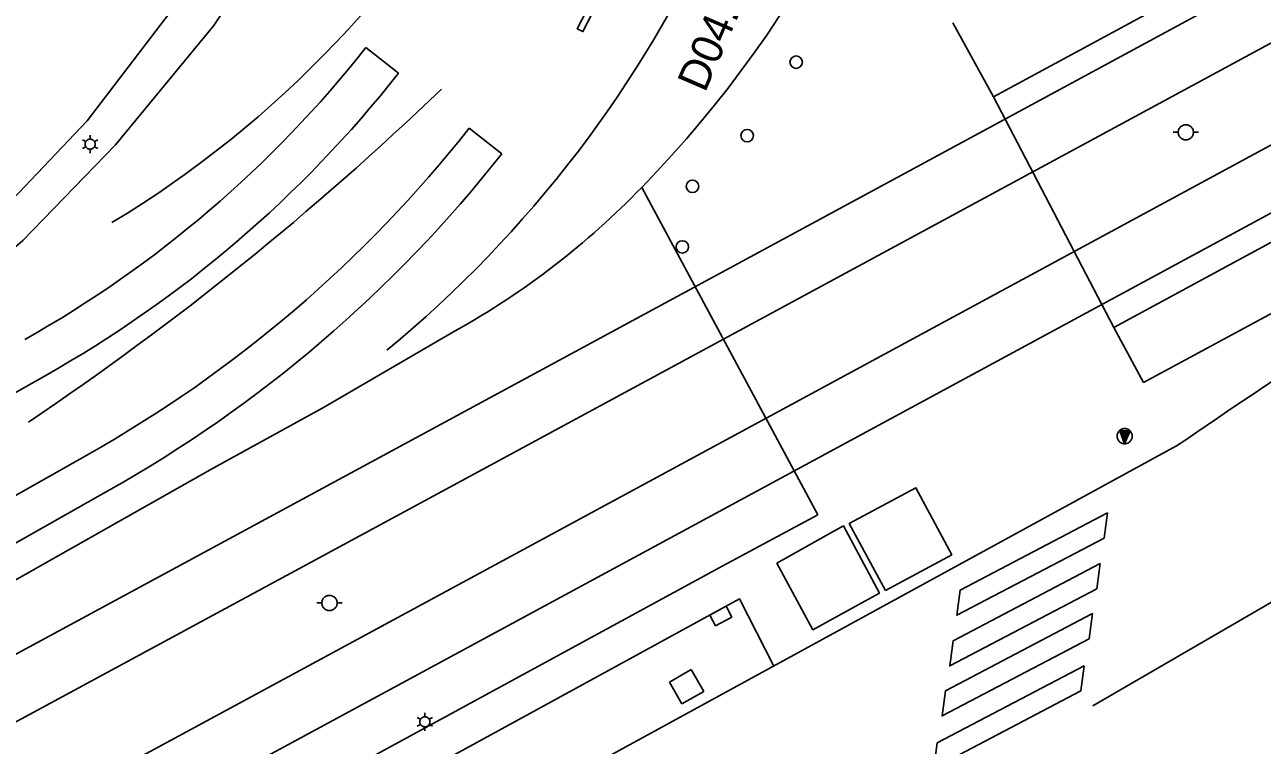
# Model space of a CAD drawing. Extents: x 81065 to 81486, y 452384 to 452681.
# Drawn here: x 81209.97 to 81239.76, y 452476.31 to 452493.67 of the extents above; entities that cross this region are included whole.
import ezdxf

# ---------------------------------------------------------------- set-up
doc = ezdxf.new("R2010")
doc.units = 0
for name, color, linetype in [('B-BH-IE-MEUBILAIR-WEGMEUBILAIR-VERKEERSBORD-S', 7, 'Continuous'), ('B-BH-IE-MEUBILAIR_WEGMEUBILAIR_LICHTMAST-S', 7, 'Continuous'), ('B-BH-IE-MEUBILAIR_WEGMEUBILAIR_PAAL-S', 7, 'Continuous'), ('B-BH-IE-MEUBILAIR_WEGMEUBILAIR_TRAMMAST-S', 7, 'Continuous'), ('B-BH-RI-GWA_RIOOLPUT-S', 7, 'Continuous'), ('B-BH-VH-KANTOPSLUITING-GV', 7, 'Continuous'), ('B-SB-OG-WEG_SPOOR_TRAM-G', 7, 'Continuous'), ('B-SRI-KOLK_COMBINATIE-S', 7, 'Continuous'), ('B-WE-VW-MARKERING_DWARS_OVERSTEEK_VOETGANGERS-G', 7, 'Continuous'), ('B-WE-VW-MARKERING_LANGS_STREEP_11_010-G', 7, 'Continuous'), ('B-WE-VW-MARKERING_LANGS_STREEP_13_010-G', 7, 'Continuous'), ('B-WE-VW-MARKERING_LANGS_STREEP_13_030-G', 7, 'Continuous'), ('B-WE-VW-MARKERING_PIJL-S', 7, 'Continuous'), ('N-OI-KL-VRI_LUS_DETECTIE-G', 7, 'Continuous'), ('N-OI-KL-VRI_LUS_DETECTIE-T18', 7, 'Continuous')]:
    doc.layers.add(name, color=color, linetype=linetype)

msp = doc.modelspace()

# ---------------------------------------------------------------- linework, layer by layer
at = {"layer": 'B-BH-IE-MEUBILAIR-WEGMEUBILAIR-VERKEERSBORD-S'}
for p, q in [((81236.318, 452483.879), (81236.583, 452483.879)), ((81236.45, 452483.57), (81236.34, 452483.861)), ((81236.34, 452483.861), (81236.555, 452483.861)), ((81236.366, 452483.843), (81236.527, 452483.843)), ((81236.451, 452483.619), (81236.366, 452483.843)), ((81236.452, 452483.668), (81236.393, 452483.824)), ((81236.393, 452483.824), (81236.499, 452483.824)), ((81236.453, 452483.717), (81236.419, 452483.806)), ((81236.419, 452483.806), (81236.472, 452483.806)), ((81236.454, 452483.765), (81236.446, 452483.788)), ((81236.583, 452483.879), (81236.45, 452483.57)), ((81236.555, 452483.861), (81236.451, 452483.619)), ((81236.527, 452483.843), (81236.452, 452483.668)), ((81236.499, 452483.824), (81236.453, 452483.717)), ((81236.472, 452483.806), (81236.454, 452483.765))]:
    msp.add_line(p, q, dxfattribs=at)
msp.add_lwpolyline([(81236.267, 452483.753), (81236.268, 452483.734), (81236.271, 452483.715), (81236.276, 452483.697), (81236.283, 452483.679), (81236.292, 452483.661), (81236.302, 452483.646), (81236.314, 452483.631), (81236.328, 452483.617), (81236.343, 452483.605), (81236.359, 452483.594), (81236.376, 452483.586), (81236.394, 452483.579), (81236.412, 452483.574), (81236.431, 452483.571), (81236.45, 452483.57), (81236.469, 452483.571), (81236.488, 452483.574), (81236.507, 452483.579), (81236.525, 452483.586), (81236.542, 452483.594), (81236.558, 452483.605), (81236.573, 452483.617), (81236.586, 452483.631), (81236.598, 452483.646), (81236.609, 452483.661), (81236.618, 452483.679), (81236.624, 452483.697), (81236.629, 452483.715), (81236.632, 452483.734), (81236.633, 452483.753), (81236.632, 452483.772), (81236.629, 452483.791), (81236.624, 452483.81), (81236.618, 452483.828), (81236.609, 452483.845), (81236.598, 452483.861), (81236.586, 452483.876), (81236.573, 452483.889), (81236.558, 452483.901), (81236.542, 452483.912), (81236.525, 452483.92), (81236.507, 452483.927), (81236.488, 452483.932), (81236.469, 452483.935), (81236.45, 452483.936), (81236.431, 452483.935), (81236.412, 452483.932), (81236.394, 452483.927), (81236.376, 452483.92), (81236.359, 452483.912), (81236.343, 452483.901), (81236.328, 452483.889), (81236.314, 452483.876), (81236.302, 452483.861), (81236.292, 452483.845), (81236.283, 452483.828), (81236.276, 452483.81), (81236.271, 452483.791), (81236.268, 452483.772), (81236.267, 452483.753)], dxfattribs=at)
at = {"layer": 'B-BH-IE-MEUBILAIR_WEGMEUBILAIR_LICHTMAST-S'}
for p, q in [((81211.437, 452490.849), (81211.358, 452490.895)), ((81211.543, 452490.91), (81211.543, 452491.002)), ((81211.648, 452490.849), (81211.728, 452490.895)), ((81211.437, 452490.727), (81211.358, 452490.681)), ((81211.543, 452490.666), (81211.543, 452490.574)), ((81211.648, 452490.727), (81211.728, 452490.681)), ((81219.497, 452476.931), (81219.418, 452476.977)), ((81219.603, 452476.992), (81219.603, 452477.084)), ((81219.708, 452476.931), (81219.788, 452476.977)), ((81219.497, 452476.809), (81219.418, 452476.763)), ((81219.603, 452476.748), (81219.603, 452476.656)), ((81219.708, 452476.809), (81219.788, 452476.763))]:
    msp.add_line(p, q, dxfattribs=at)
for points in [[(81211.421, 452490.788), (81211.422, 452490.775), (81211.423, 452490.762), (81211.427, 452490.75), (81211.431, 452490.738), (81211.437, 452490.727), (81211.444, 452490.716), (81211.452, 452490.706), (81211.461, 452490.697), (81211.471, 452490.689), (81211.482, 452490.682), (81211.493, 452490.676), (81211.505, 452490.672), (81211.518, 452490.668), (81211.53, 452490.667), (81211.543, 452490.666), (81211.556, 452490.667), (81211.568, 452490.668), (81211.581, 452490.672), (81211.593, 452490.676), (81211.604, 452490.682), (81211.615, 452490.689), (81211.625, 452490.697), (81211.634, 452490.706), (81211.642, 452490.716), (81211.649, 452490.727), (81211.654, 452490.738), (81211.659, 452490.75), (81211.662, 452490.762), (81211.664, 452490.775), (81211.665, 452490.788), (81211.664, 452490.801), (81211.662, 452490.813), (81211.659, 452490.826), (81211.654, 452490.838), (81211.649, 452490.849), (81211.642, 452490.86), (81211.634, 452490.87), (81211.625, 452490.879), (81211.615, 452490.887), (81211.604, 452490.894), (81211.593, 452490.899), (81211.581, 452490.904), (81211.568, 452490.907), (81211.556, 452490.909), (81211.543, 452490.91), (81211.53, 452490.909), (81211.517, 452490.907), (81211.505, 452490.904), (81211.493, 452490.899), (81211.482, 452490.894), (81211.471, 452490.887), (81211.461, 452490.879), (81211.452, 452490.87), (81211.444, 452490.86), (81211.437, 452490.849), (81211.431, 452490.838), (81211.427, 452490.826), (81211.423, 452490.813), (81211.422, 452490.801), (81211.421, 452490.788)], [(81219.481, 452476.87), (81219.482, 452476.857), (81219.483, 452476.844), (81219.487, 452476.832), (81219.491, 452476.82), (81219.497, 452476.809), (81219.504, 452476.798), (81219.512, 452476.788), (81219.521, 452476.779), (81219.531, 452476.771), (81219.542, 452476.764), (81219.553, 452476.758), (81219.565, 452476.754), (81219.578, 452476.75), (81219.59, 452476.749), (81219.603, 452476.748), (81219.616, 452476.749), (81219.628, 452476.75), (81219.641, 452476.754), (81219.653, 452476.758), (81219.664, 452476.764), (81219.675, 452476.771), (81219.685, 452476.779), (81219.694, 452476.788), (81219.702, 452476.798), (81219.709, 452476.809), (81219.714, 452476.82), (81219.719, 452476.832), (81219.722, 452476.844), (81219.724, 452476.857), (81219.725, 452476.87), (81219.724, 452476.883), (81219.722, 452476.895), (81219.719, 452476.908), (81219.714, 452476.92), (81219.709, 452476.931), (81219.702, 452476.942), (81219.694, 452476.952), (81219.685, 452476.961), (81219.675, 452476.969), (81219.664, 452476.976), (81219.653, 452476.981), (81219.641, 452476.986), (81219.628, 452476.989), (81219.616, 452476.991), (81219.603, 452476.992), (81219.59, 452476.991), (81219.577, 452476.989), (81219.565, 452476.986), (81219.553, 452476.981), (81219.542, 452476.976), (81219.531, 452476.969), (81219.521, 452476.961), (81219.512, 452476.952), (81219.504, 452476.942), (81219.497, 452476.931), (81219.491, 452476.92), (81219.487, 452476.908), (81219.483, 452476.895), (81219.482, 452476.883), (81219.481, 452476.87)]]:
    msp.add_lwpolyline(points, dxfattribs=at)
at = {"layer": 'B-BH-IE-MEUBILAIR_WEGMEUBILAIR_PAAL-S'}
for centre in [(81228.543, 452492.763), (81227.363, 452490.993), (81226.047, 452489.772), (81225.803, 452488.313)]:
    msp.add_circle(centre, 0.15, dxfattribs=at)
at = {"layer": 'B-BH-IE-MEUBILAIR_WEGMEUBILAIR_TRAMMAST-S'}
for p, q in [((81237.741, 452491.074), (81237.619, 452491.074)), ((81238.229, 452491.074), (81238.107, 452491.074)), ((81217.122, 452479.734), (81217, 452479.734)), ((81217.61, 452479.734), (81217.488, 452479.734))]:
    msp.add_line(p, q, dxfattribs=at)
for points in [[(81237.741, 452491.074), (81237.742, 452491.055), (81237.745, 452491.036), (81237.75, 452491.017), (81237.757, 452490.999), (81237.765, 452490.982), (81237.776, 452490.966), (81237.788, 452490.951), (81237.801, 452490.938), (81237.816, 452490.926), (81237.832, 452490.915), (81237.849, 452490.907), (81237.867, 452490.9), (81237.886, 452490.895), (81237.905, 452490.892), (81237.924, 452490.891), (81237.943, 452490.892), (81237.962, 452490.895), (81237.981, 452490.9), (81237.998, 452490.907), (81238.015, 452490.915), (81238.032, 452490.926), (81238.046, 452490.938), (81238.06, 452490.951), (81238.072, 452490.966), (81238.082, 452490.982), (81238.091, 452490.999), (81238.098, 452491.017), (81238.103, 452491.036), (81238.106, 452491.055), (81238.107, 452491.074), (81238.106, 452491.093), (81238.103, 452491.112), (81238.098, 452491.131), (81238.091, 452491.148), (81238.082, 452491.165), (81238.072, 452491.182), (81238.06, 452491.196), (81238.046, 452491.21), (81238.032, 452491.222), (81238.015, 452491.232), (81237.998, 452491.241), (81237.981, 452491.248), (81237.962, 452491.253), (81237.943, 452491.256), (81237.924, 452491.257), (81237.905, 452491.256), (81237.886, 452491.253), (81237.867, 452491.248), (81237.849, 452491.241), (81237.832, 452491.232), (81237.816, 452491.222), (81237.801, 452491.21), (81237.788, 452491.196), (81237.776, 452491.182), (81237.765, 452491.165), (81237.757, 452491.148), (81237.75, 452491.131), (81237.745, 452491.112), (81237.742, 452491.093), (81237.741, 452491.074)], [(81217.122, 452479.734), (81217.123, 452479.715), (81217.126, 452479.696), (81217.131, 452479.677), (81217.138, 452479.659), (81217.146, 452479.642), (81217.157, 452479.626), (81217.169, 452479.611), (81217.182, 452479.598), (81217.197, 452479.586), (81217.213, 452479.575), (81217.23, 452479.567), (81217.248, 452479.56), (81217.267, 452479.555), (81217.286, 452479.552), (81217.305, 452479.551), (81217.324, 452479.552), (81217.343, 452479.555), (81217.362, 452479.56), (81217.379, 452479.567), (81217.396, 452479.575), (81217.413, 452479.586), (81217.427, 452479.598), (81217.441, 452479.611), (81217.453, 452479.626), (81217.463, 452479.642), (81217.472, 452479.659), (81217.479, 452479.677), (81217.484, 452479.696), (81217.487, 452479.715), (81217.488, 452479.734), (81217.487, 452479.753), (81217.484, 452479.772), (81217.479, 452479.791), (81217.472, 452479.808), (81217.463, 452479.825), (81217.453, 452479.842), (81217.441, 452479.856), (81217.427, 452479.87), (81217.413, 452479.882), (81217.396, 452479.892), (81217.379, 452479.901), (81217.362, 452479.908), (81217.343, 452479.913), (81217.324, 452479.916), (81217.305, 452479.917), (81217.286, 452479.916), (81217.267, 452479.913), (81217.248, 452479.908), (81217.23, 452479.901), (81217.213, 452479.892), (81217.197, 452479.882), (81217.182, 452479.87), (81217.169, 452479.856), (81217.157, 452479.842), (81217.146, 452479.825), (81217.138, 452479.808), (81217.131, 452479.791), (81217.126, 452479.772), (81217.123, 452479.753), (81217.122, 452479.734)]]:
    msp.add_lwpolyline(points, dxfattribs=at)
at = {"layer": 'B-BH-RI-GWA_RIOOLPUT-S'}
for p, q in [((81226.018, 452478.128), (81225.491, 452477.827)), ((81226.32, 452477.602), (81226.018, 452478.128)), ((81225.491, 452477.827), (81225.793, 452477.3)), ((81225.793, 452477.3), (81226.32, 452477.602))]:
    msp.add_line(p, q, dxfattribs=at)
at = {"layer": 'B-BH-VH-KANTOPSLUITING-GV'}
for p, q in [((81233.291, 452491.927), (81250, 452500.979)), ((81250, 452493.854), (81236.189, 452486.374)), ((81236.906, 452485.042), (81250, 452492.137)), ((81233.291, 452491.927), (81236.189, 452486.374)), ((81229.065, 452481.856), (81224.825, 452489.748)), ((81236.189, 452486.374), (81236.906, 452485.042))]:
    msp.add_line(p, q, dxfattribs=at)
for points in [[(81215.184, 452496.736), (81213.682, 452494.242), (81211.474, 452491.348), (81209.365, 452489.136), (81206.477, 452486.625), (81203.342, 452484.43), (81199.995, 452482.573), (81157.091, 452458.458), (81156.072, 452457.868), (81151.131, 452454.729), (81146.282, 452451.196), (81140.808, 452446.932)], [(81141.843, 452446.719), (81147.942, 452451.449), (81151.636, 452454.16), (81156.157, 452457.017), (81157.59, 452457.827), (81191.478, 452476.863), (81200.364, 452481.854), (81203.771, 452483.726), (81206.967, 452485.937), (81209.919, 452488.465), (81212.154, 452490.776), (81214.522, 452493.647), (81216.352, 452496.426)], [(81232.312, 452493.712), (81233.291, 452491.927)], [(81220.335, 452486.293), (81217.165, 452484.447), (81214.437, 452482.941), (81207.347, 452478.935), (81194.35, 452471.616), (81162.041, 452453.42), (81156.047, 452449.726), (81150.272, 452445.697), (81149.556, 452445.135)], [(81166.505, 452441.653), (81172.172, 452445.873), (81172.7, 452446.254), (81172.867, 452446.35), (81180.693, 452451.592), (81188.735, 452456.496), (81192.385, 452458.571), (81202.855, 452464.464), (81237.7, 452483.516)], [(81230.689, 452480.038), (81229.821, 452481.648), (81231.427, 452482.505), (81232.288, 452480.894), (81230.689, 452480.038)], [(81162.668, 452442.441), (81169.895, 452447.714), (81170.064, 452447.811), (81171.72, 452449.007), (81177.948, 452453.188), (81182.8, 452456.219), (81191.033, 452460.983), (81205.552, 452469.075), (81226.775, 452480.625), (81229.065, 452481.856)], [(81230.198, 452479.775), (81230.548, 452479.967), (81229.679, 452481.589), (81229.32, 452481.388)], [(81229.32, 452481.388), (81228.077, 452480.692), (81228.946, 452479.087), (81230.198, 452479.775)], [(81228.003, 452478.214), (81227.178, 452479.831), (81204.778, 452467.581), (81194.026, 452461.655), (81191.474, 452460.18), (81186.357, 452457.208), (81179.07, 452452.739), (81171.84, 452447.862), (81171.561, 452447.682), (81164.068, 452442.154)]]:
    msp.add_lwpolyline(points, dxfattribs=at)
for centre, radius, start, end in [((81204.782, 452509.244), 27.961, 315.7914, 350.3166), ((81364.383, 452298.915), 223.889, 119.58237, 124.46006), ((81210.901, 452503.2), 19.361, 299.1621, 315.9877)]:
    msp.add_arc(centre, radius, start, end, dxfattribs=at)
at = {"layer": 'B-SB-OG-WEG_SPOOR_TRAM-G'}
for p, q in [((81250, 452500.286), (81195.496, 452470.783)), ((81250, 452498.654), (81196.18, 452469.521)), ((81198.781, 452468.467), (81250, 452496.192)), ((81199.465, 452467.205), (81250, 452494.56))]:
    msp.add_line(p, q, dxfattribs=at)
at = {"layer": 'B-SRI-KOLK_COMBINATIE-S'}
for p, q in [((81226.853, 452479.655), (81226.461, 452479.44)), ((81226.995, 452479.396), (81226.853, 452479.655)), ((81226.461, 452479.44), (81226.602, 452479.181)), ((81226.602, 452479.181), (81226.995, 452479.396))]:
    msp.add_line(p, q, dxfattribs=at)
at = {"layer": 'B-WE-VW-MARKERING_DWARS_OVERSTEEK_VOETGANGERS-G'}
for points in [[(81236.035, 452481.903), (81232.493, 452480.044), (81232.413, 452479.438), (81235.955, 452481.297)], [(81235.862, 452480.682), (81232.32, 452478.823), (81232.24, 452478.216), (81235.781, 452480.075)], [(81235.679, 452479.48), (81232.137, 452477.621), (81232.057, 452477.014), (81235.599, 452478.873)], [(81235.475, 452478.222), (81231.933, 452476.363), (81231.853, 452475.756), (81235.395, 452477.615)]]:
    msp.add_lwpolyline(points, close=True, dxfattribs=at)
at = {"layer": 'B-WE-VW-MARKERING_LANGS_STREEP_11_010-G'}
msp.add_line((81235.683, 452477.252), (81243.497, 452481.8), dxfattribs=at)
at = {"layer": 'B-WE-VW-MARKERING_LANGS_STREEP_13_010-G'}
msp.add_arc((81168.978, 452545.195), 73.627, 303.91282, 313.86631, dxfattribs=at)
at = {"layer": 'B-WE-VW-MARKERING_LANGS_STREEP_13_030-G'}
for centre, radius, start, end in [((81198.778, 452510.937), 25.735, 301.091, 332.0351), ((81200.266, 452508.145), 28.94, 309.535, 335.7286)]:
    msp.add_arc(centre, radius, start, end, dxfattribs=at)
at = {"layer": 'B-WE-VW-MARKERING_PIJL-S'}
msp.add_lwpolyline([(81225.631, 452497.977), (81224.359, 452496.327), (81224.625, 452496.19), (81223.273, 452493.568), (81223.407, 452493.499), (81224.758, 452496.121), (81225.025, 452495.984)], close=True, dxfattribs=at)
at = {"layer": 'N-OI-KL-VRI_LUS_DETECTIE-G'}
for p, q in [((81218.967, 452492.496), (81218.182, 452493.115)), ((81221.456, 452490.557), (81220.671, 452491.176))]:
    msp.add_line(p, q, dxfattribs=at)
for points in [[(81203.215, 452481.119), (81204.597, 452481.897), (81210.461, 452485.21)], [(81211.481, 452483.306), (81205.618, 452479.993), (81204.237, 452479.215)], [(81204.728, 452478.344), (81206.109, 452479.122), (81211.973, 452482.435)]]:
    msp.add_lwpolyline(points, dxfattribs=at)
for centre, radius, end in [((81196.314, 452510.336), 27.834, 321.7787), ((81196.314, 452510.336), 28.834, 321.7781), ((81196.202, 452510.447), 31.146, 321.777), ((81196.202, 452510.447), 32.146, 321.7766)]:
    msp.add_arc(centre, radius, 299.3791, end, dxfattribs=at)

# ---------------------------------------------------------------- texts
at = {"layer": 'N-OI-KL-VRI_LUS_DETECTIE-T18'}
msp.add_text('D04.2', height=0.75, rotation=66.6069, dxfattribs=at).set_placement((81226.347, 452492.01))

doc.saveas('drawing.dxf')
